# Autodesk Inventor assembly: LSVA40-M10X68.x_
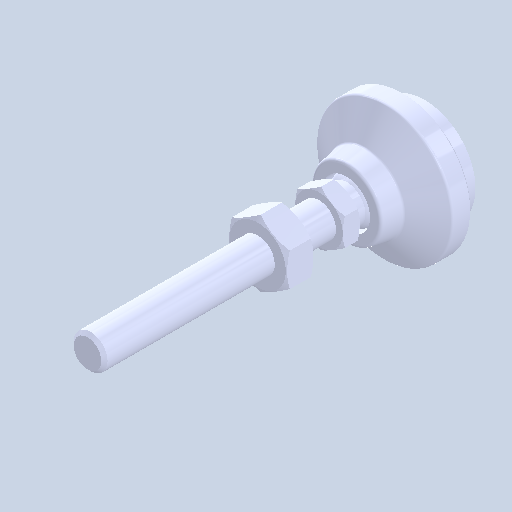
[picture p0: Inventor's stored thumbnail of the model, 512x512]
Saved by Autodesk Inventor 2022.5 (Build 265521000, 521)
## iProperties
Created: 2024-08
Part Number: LSVA40-M10X68.x_
Document SubType Name: Assembly
Designer: ImaoCorp
Author: ImaoCorp
Sending System: SOLIDWORKS 2022-2022290
MC: AMD64
MC_MODEL: Intel64 Family 6 Model 60 Stepping 3, GenuineIntel
OS: Windows_NT
FRU: Parasolid Version 33.1, build 260,  4-25-2022
FORMAT: text
GUISE: transmit
KEY: FILELSVA40-M10X68.x_t
DATE: Fri Aug 23 16:07:16 2024
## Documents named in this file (4)
- X:\14_SW2022-Inv2022\06_2024-10新製品(SME)\ELS_データ\l\lsva40-m10x68\LSVA40-M10X68.x_.iam
- X:\14_SW2022-Inv2022\06_2024-10新製品(SME)\ELS_データ\l\lsva40-m10x68\LSVA40-M10X68_01.ipt
- X:\14_SW2022-Inv2022\06_2024-10新製品(SME)\ELS_データ\l\lsva40-m10x68\LSVA40-M10X68_02.ipt
- X:\14_SW2022-Inv2022\06_2024-10新製品(SME)\ELS_データ\l\lsva40-m10x68\LSVA40-M10X68_03.ipt
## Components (3 placed, 3 different names)
1. LSVA40-M10X68_01
2. LSVA40-M10X68_02
3. LSVA40-M10X68_03
